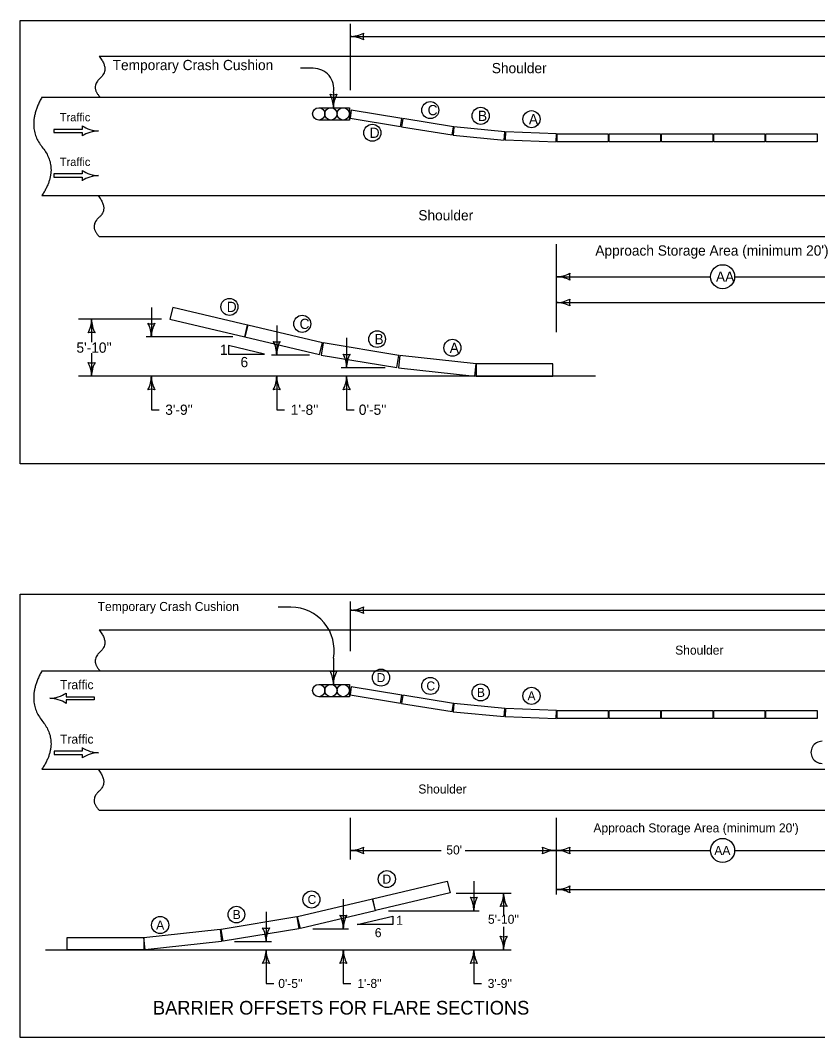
# Model space of a CAD drawing. Extents: x 8045 to 81668, y 6217 to 16762.
# Drawn here: x 13748 to 14916, y 6217 to 7708 of the extents above; entities that cross this region are included whole.
import ezdxf

# ---------------------------------------------------------------- set-up
doc = ezdxf.new("R2010")
doc.units = 0
for name, color, linetype in [('dsnNonPlotable', 7, 'Continuous'), ('dsnStdBlock', 7, 'Continuous'), ('dsnStdBlockModified', 7, 'Continuous'), ('dsnStdBorder', 7, 'Continuous'), ('dsnStdLineWork', 7, 'Continuous'), ('Level 5', 7, 'Continuous')]:
    doc.layers.add(name, color=color, linetype=linetype)

msp = doc.modelspace()

# ---------------------------------------------------------------- linework, layer by layer
at = {"layer": 'dsnNonPlotable'}
for p, q in [((14230.5, 7703.1), (14230.5, 7605.6)), ((14230.5, 7684.4), (15109, 7684.4)), ((13862.8, 7655.5), (14991.3, 7655.5)), ((14176.7, 7637.8), (14158, 7637.8)), ((13779.2, 7595.5), (15021.3, 7595.5)), ((14206.2, 7602.4), (14206.2, 7579.9)), ((14184.6, 7579.9), (14229.6, 7579.9)), ((14229.6, 7579.9), (14229.6, 7561.9)), ((14229.6, 7561.9), (14184.6, 7561.9)), ((14228.4, 7567.6), (14229.7, 7567.3)), ((14230.1, 7563.9), (14230.1, 7563.9)), ((13838.1, 7548.3), (13796.8, 7548.3)), ((13796.8, 7548.3), (13796.8, 7543.8)), ((13796.8, 7543.8), (13838.1, 7543.8)), ((13838.1, 7553.6), (13838.1, 7548.3)), ((13838.1, 7543.8), (13838.1, 7538.6)), ((13862, 7546.1), (13862, 7546.1)), ((13838.1, 7488.1), (13838.1, 7482.9)), ((13838.1, 7482.9), (13796.8, 7482.9)), ((13796.8, 7482.9), (13796.8, 7478.4)), ((13796.8, 7478.4), (13838.1, 7478.4)), ((13838.1, 7478.4), (13838.1, 7473.1)), ((13862, 7480.6), (13862, 7480.6)), ((13779.2, 7451.5), (15021.3, 7451.5)), ((13862.8, 7391.5), (14991.3, 7391.5)), ((14532.6, 7380.2), (14532.6, 7251.1)), ((14532.6, 7332.4), (14758.7, 7332.4)), ((14794, 7332.4), (15020.1, 7332.4)), ((14532.6, 7294.5), (15123.4, 7294.5)), ((13939.5, 7287.5), (13939.5, 7244.1)), ((13954.1, 7270), (13832.9, 7270)), ((13851.9, 7270), (13851.9, 7236.6)), ((14123.1, 7261.1), (14123.1, 7217.6)), ((14059, 7244.1), (13931.8, 7244.1)), ((14225.5, 7242.6), (14225.5, 7199.1)), ((13851.9, 7220.2), (13851.9, 7186.8)), ((14170.9, 7217.6), (14115.3, 7217.6)), ((14590.3, 7186.8), (13832.9, 7186.8)), ((13939.5, 7186.8), (13939.5, 7137.5)), ((14123.1, 7186.8), (14123.1, 7137.5)), ((14281.8, 7199.1), (14217.7, 7199.1)), ((14225.5, 7186.8), (14225.5, 7159.8)), ((14225.5, 7159.8), (14225.5, 7137.5)), ((13939.5, 7137.5), (13950.7, 7137.5)), ((14123.1, 7137.5), (14134.3, 7137.5)), ((14225.5, 7137.5), (14236.6, 7137.5))]:
    msp.add_line(p, q, dxfattribs=at)
for points in [[(14306.4, 7564.3), (14232.4, 7576.4), (14230.5, 7564.6), (14304.5, 7552.4)], [(14381.9, 7551.9), (14307.9, 7564), (14306, 7552.2), (14380, 7540.1)], [(14457.3, 7544.7), (14382.7, 7551.8), (14381.5, 7539.8), (14456.2, 7532.7)], [(14533.1, 7541.7), (14458.2, 7544.7), (14457.7, 7532.8), (14532.6, 7529.8)], [(14533.8, 7541.8), (14608.8, 7541.8), (14608.8, 7529.8), (14533.8, 7529.8)], [(14610.3, 7541.8), (14685.3, 7541.8), (14685.3, 7529.8), (14610.3, 7529.8)], [(14686.8, 7541.8), (14761.8, 7541.8), (14761.8, 7529.8), (14686.8, 7529.8)], [(14763.3, 7541.8), (14838.3, 7541.8), (14838.3, 7529.8), (14763.3, 7529.8)], [(14839.8, 7541.8), (14914.8, 7541.8), (14914.8, 7529.8), (14839.8, 7529.8)], [(14080.3, 7261.6), (13970.9, 7287.5), (13966.7, 7270), (14076.2, 7244.1)], [(14190.1, 7235.7), (14080.6, 7261.6), (14076.5, 7244.1), (14186, 7218.2)], [(14302.2, 7217), (14191.2, 7235.4), (14188.3, 7217.6), (14299.2, 7199.2)], [(14415.3, 7204.6), (14303.5, 7217), (14301.5, 7199.1), (14413.3, 7186.8)], [(14527.8, 7204.8), (14415.3, 7204.8), (14415.3, 7186.8), (14527.8, 7186.8)]]:
    msp.add_lwpolyline(points, close=True, dxfattribs=at)
for centre, radius in [((14348.1, 7576.5), 12.5), ((14184.6, 7570.9), 9), ((14184.6, 7570.9), 9), ((14202.6, 7570.9), 9), ((14202.6, 7570.9), 9), ((14220.6, 7570.9), 9), ((14220.6, 7570.9), 9), ((14421.9, 7568.1), 12.5), ((14496.4, 7563.2), 12.5), ((14263.2, 7543.3), 12.5), ((14776.4, 7332.4), 17.6), ((14053.8, 7288.2), 12.5), ((14160.5, 7263.3), 12.5), ((14270.2, 7240.9), 12.2), ((14380.5, 7228.3), 12.5)]:
    msp.add_circle(centre, radius, dxfattribs=at)
for centre, radius, start, end in [((14230.5, 7726.9), 42.5, 270, 298.0725), ((14230.5, 7641.9), 42.5, 61.9275, 90), ((14266.1, 7684.4), 16.4, 162.2666, 197.7334), ((14176.7, 7607.8), 30, 349.6463, 90), ((14206.2, 7615.5), 16.4, 252.2666, 287.7333), ((14163.7, 7579.9), 42.5, 360, 28.0725), ((14248.7, 7579.9), 42.5, 151.9275, 180), ((13864, 7594.4), 48.4, 237.618, 267.648), ((13864, 7497.7), 48.4, 92.352, 122.382), ((13864, 7528.9), 48.4, 237.618, 267.648), ((13864, 7432.3), 48.4, 92.352, 122.382), ((14532.6, 7374.9), 42.5, 270, 298.0725), ((14568.3, 7332.4), 16.4, 162.2666, 197.7334), ((14532.6, 7289.9), 42.5, 61.9275, 90), ((14532.6, 7337), 42.5, 270, 298.0725), ((14532.6, 7252), 42.5, 61.9275, 90), ((14568.3, 7294.5), 16.4, 162.2666, 197.7334), ((13809.4, 7270), 42.5, 331.9275, 0), ((13894.4, 7270), 42.5, 180, 208.0725), ((13939.5, 7279.7), 16.4, 252.2666, 287.7334), ((13897, 7244.1), 42.5, 0, 28.0725), ((13982, 7244.1), 42.5, 151.9275, 180), ((13851.9, 7234.4), 16.4, 72.2666, 107.7334), ((14123.1, 7253.3), 16.4, 252.2666, 287.7334), ((14080.6, 7217.6), 42.5, 0, 28.0725), ((14165.6, 7217.6), 42.5, 151.9275, 180), ((14225.5, 7234.7), 16.4, 252.2666, 287.7334), ((14183, 7199.1), 42.5, 0, 28.0725), ((14268, 7199.1), 42.5, 151.9275, 180), ((13851.9, 7222.4), 16.4, 252.2666, 287.7334), ((13809.4, 7186.8), 42.5, 0, 28.0725), ((13894.4, 7186.8), 42.5, 151.9275, 180), ((13897, 7186.8), 42.5, 331.9275, 0), ((13982, 7186.8), 42.5, 180, 208.0725), ((14080.6, 7186.8), 42.5, 331.9275, 0), ((14165.6, 7186.8), 42.5, 180, 208.0725), ((14183, 7186.8), 42.5, 331.9275, 0), ((14268, 7186.8), 42.5, 180, 208.0725), ((13939.5, 7151.1), 16.4, 72.2666, 107.7334), ((14123.1, 7151.1), 16.4, 72.2666, 107.7334), ((14225.5, 7151.1), 16.4, 72.2666, 107.7334)]:
    msp.add_arc(centre, radius, start, end, dxfattribs=at)
for points in [[(13862.8, 7655.5), (13878.9, 7636.1), (13850, 7610.5), (13864.4, 7595.5)], [(13779.2, 7595.5), (13754.6, 7552.8), (13805.3, 7490.6), (13779.2, 7451.5)], [(13861.2, 7451.4), (13877.3, 7432.1), (13848.4, 7406.5), (13862.8, 7391.5)]]:
    msp.add_open_spline(points, degree=2, dxfattribs=at)
at = {"layer": 'dsnStdBlock'}
msp.add_line((13747.5, 7708), (13747.5, 7708), dxfattribs=at)
at = {"layer": 'dsnStdBlockModified'}
for p, q in [((13747.5, 7708), (16852.5, 7708)), ((13747.5, 7058), (13747.5, 7708))]:
    msp.add_line(p, q, dxfattribs=at)
at = {"layer": 'dsnStdBorder'}
msp.add_line((16852.5, 7058), (13747.5, 7058), dxfattribs=at)
at = {"layer": 'dsnStdLineWork'}
for p, q in [((13747.5, 6867.4), (16852.5, 6867.4)), ((13747.5, 6217.4), (13747.5, 6867.4)), ((14143.9, 6848.2), (14125.2, 6848.2)), ((14230.5, 6856.5), (14230.5, 6783.9)), ((14230.5, 6843.7), (15163.3, 6843.7)), ((13862.8, 6814.8), (14991.3, 6814.8)), ((14206.2, 6773.5), (14206.2, 6734.9)), ((13779.2, 6754.8), (15021.3, 6754.8)), ((14184.6, 6734.9), (14229.6, 6734.9)), ((14229.6, 6734.9), (14229.6, 6716.9)), ((13790.7, 6714.6), (13790.7, 6714.6)), ((13814.6, 6722.1), (13814.6, 6716.9)), ((13814.6, 6716.9), (13855.9, 6716.9)), ((13855.9, 6712.4), (13814.6, 6712.4)), ((13814.6, 6712.4), (13814.6, 6707.1)), ((13855.9, 6716.9), (13855.9, 6712.4)), ((14229.6, 6716.9), (14184.6, 6716.9)), ((14228.4, 6722.6), (14229.7, 6722.3)), ((14230.1, 6718.9), (14230.1, 6718.9)), ((13838.3, 6637), (13797, 6637)), ((13797, 6637), (13797, 6632.5)), ((13838.3, 6642.3), (13838.3, 6637)), ((13862.2, 6634.8), (13862.2, 6634.8)), ((13797, 6632.5), (13838.3, 6632.5)), ((13838.3, 6632.5), (13838.3, 6627.3)), ((13779.2, 6610.8), (15021.3, 6610.8)), ((13862.8, 6550.8), (14991.3, 6550.8)), ((14230.5, 6539.5), (14230.5, 6478.3)), ((14532.6, 6539.5), (14532.6, 6427.1)), ((14230.5, 6491.7), (14363.9, 6491.7)), ((14399.2, 6491.7), (14532.6, 6491.7)), ((14532.6, 6491.7), (14758.7, 6491.7)), ((14794, 6491.7), (15020.1, 6491.7)), ((14411.9, 6446.8), (14411.9, 6403.4)), ((14386, 6429.3), (14466.4, 6429.3)), ((14455.5, 6429.3), (14455.5, 6395.9)), ((14532.6, 6434.6), (15123.4, 6434.6)), ((14220.7, 6420.4), (14220.7, 6377)), ((14107.5, 6401.9), (14107.5, 6358.4)), ((14240.8, 6383), (14293.4, 6395.4)), ((14287, 6403.4), (14419.7, 6403.4)), ((14293.4, 6395.4), (14293.4, 6383)), ((14293.4, 6383), (14240.8, 6383)), ((14175.8, 6377), (14228.5, 6377)), ((14455.5, 6379.5), (14455.5, 6346.1)), ((14061.5, 6358.4), (14115.3, 6358.4)), ((13784.5, 6346.1), (14466.4, 6346.1)), ((14107.5, 6346.1), (14107.5, 6319.1)), ((14220.7, 6346.1), (14220.7, 6296.8)), ((14411.9, 6346.1), (14411.9, 6296.8)), ((14107.5, 6319.1), (14107.5, 6296.8)), ((14107.5, 6296.8), (14118.7, 6296.8)), ((14220.7, 6296.8), (14231.9, 6296.8)), ((14411.9, 6296.8), (14423, 6296.8)), ((16852.5, 6217.4), (13747.5, 6217.4))]:
    msp.add_line(p, q, dxfattribs=at)
for points in [[(14306.4, 6719.3), (14232.4, 6731.4), (14230.5, 6719.6), (14304.5, 6707.5)], [(14381.9, 6706.9), (14307.9, 6719.1), (14306, 6707.2), (14380, 6695.1)], [(14457.3, 6699.7), (14382.7, 6706.8), (14381.5, 6694.9), (14456.2, 6687.8)], [(14533.1, 6696.8), (14458.2, 6699.8), (14457.7, 6687.8), (14532.6, 6684.8)], [(14533.8, 6696.8), (14608.8, 6696.8), (14608.8, 6684.8), (14533.8, 6684.8)], [(14610.3, 6696.8), (14685.3, 6696.8), (14685.3, 6684.8), (14610.3, 6684.8)], [(14686.8, 6696.8), (14761.8, 6696.8), (14761.8, 6684.8), (14686.8, 6684.8)], [(14763.3, 6696.8), (14838.3, 6696.8), (14838.3, 6684.8), (14763.3, 6684.8)], [(14839.8, 6696.8), (14914.8, 6696.8), (14914.8, 6684.8), (14839.8, 6684.8)], [(14263.5, 6421), (14373, 6446.9), (14377.2, 6429.4), (14267.7, 6403.5)], [(14153.7, 6395), (14263.2, 6420.9), (14267.3, 6403.4), (14157.9, 6377.5)], [(14041.6, 6376.3), (14152.6, 6394.7), (14155.6, 6377), (14044.6, 6358.5)], [(13928.5, 6364), (14040.4, 6376.3), (14042.3, 6358.4), (13930.5, 6346.1)], [(13816, 6364.2), (13928.5, 6364.1), (13928.5, 6346.1), (13816, 6346.2)]]:
    msp.add_lwpolyline(points, close=True, dxfattribs=at)
for centre, radius in [((14275.9, 6744.9), 12.5), ((14348.1, 6732.7), 12.5), ((14184.6, 6725.9), 9), ((14184.6, 6725.9), 9), ((14202.6, 6725.9), 9), ((14202.6, 6725.9), 9), ((14220.6, 6725.9), 9), ((14220.6, 6725.9), 9), ((14421.9, 6723.2), 12.5), ((14496.4, 6718.2), 12.5), ((14776.4, 6491.7), 17.6), ((14284.4, 6449.7), 12.5), ((14174, 6419.8), 12.5), ((14064, 6397.7), 12.2), ((13952.4, 6382.4), 12.5)]:
    msp.add_circle(centre, radius, dxfattribs=at)
for centre, radius, start, end in [((14143.9, 6784.9), 63.3, 349.6463, 90), ((14230.5, 6886.2), 42.5, 270, 298.0725), ((14230.5, 6801.2), 42.5, 61.9275, 90), ((14266.1, 6843.7), 16.4, 162.2666, 197.7334), ((14206.2, 6770.5), 16.4, 252.2666, 287.7333), ((14163.7, 6734.9), 42.5, 360, 28.0725), ((14248.7, 6734.9), 42.5, 151.9275, 180), ((13788.7, 6763), 48.4, 272.352, 302.382), ((13788.7, 6666.3), 48.4, 57.618, 87.648), ((13864.2, 6683.1), 48.4, 237.618, 267.648), ((13864.2, 6586.5), 48.4, 92.352, 122.382), ((14230.5, 6534.2), 42.5, 270, 298.0725), ((14230.5, 6449.2), 42.5, 61.9275, 90), ((14266.1, 6491.7), 16.4, 162.2666, 197.7334), ((14497, 6491.7), 16.4, 342.2666, 17.7333), ((14532.6, 6534.2), 42.5, 241.9275, 270), ((14532.6, 6449.2), 42.5, 90, 118.0725), ((14532.6, 6534.2), 42.5, 270, 298.0725), ((14532.6, 6449.2), 42.5, 61.9275, 90), ((14568.3, 6491.7), 16.4, 162.2666, 197.7334), ((14413, 6429.3), 42.5, 331.9275, 360), ((14498, 6429.3), 42.5, 180, 208.0725), ((14532.6, 6477.1), 42.5, 270, 298.0725), ((14532.6, 6392.1), 42.5, 61.9275, 90), ((14568.3, 6434.6), 16.4, 162.2666, 197.7334), ((14411.9, 6439), 16.4, 252.2666, 287.7333), ((14369.4, 6403.4), 42.5, 360, 28.0725), ((14454.4, 6403.4), 42.5, 151.9275, 180), ((14455.5, 6393.7), 16.4, 72.2666, 107.7334), ((14220.7, 6412.6), 16.4, 252.2666, 287.7333), ((14178.2, 6377), 42.5, 360, 28.0725), ((14263.2, 6377), 42.5, 151.9275, 180), ((14107.5, 6394), 16.4, 252.2666, 287.7333), ((14065, 6358.4), 42.5, 360, 28.0725), ((14150, 6358.4), 42.5, 151.9275, 180), ((14455.5, 6381.7), 16.4, 252.2666, 287.7333), ((14413, 6346.1), 42.5, 360, 28.0725), ((14498, 6346.1), 42.5, 151.9275, 180), ((14065, 6346.1), 42.5, 331.9275, 360), ((14150, 6346.1), 42.5, 180, 208.0725), ((14178.2, 6346.1), 42.5, 331.9275, 360), ((14263.2, 6346.1), 42.5, 180, 208.0725), ((14369.4, 6346.1), 42.5, 331.9275, 360), ((14454.4, 6346.1), 42.5, 180, 208.0725), ((14107.5, 6310.4), 16.4, 72.2666, 107.7334), ((14220.7, 6310.4), 16.4, 72.2666, 107.7334), ((14411.9, 6310.4), 16.4, 72.2666, 107.7334)]:
    msp.add_arc(centre, radius, start, end, dxfattribs=at)
msp.add_ellipse((14922.1, 6635.4), major_axis=(-16.3, 0), ratio=0.995025, start_param=4.712389, end_param=7.853982, dxfattribs=at)
for points in [[(13862.8, 6814.8), (13878.9, 6795.5), (13850, 6769.8), (13864.4, 6754.8)], [(13779.2, 6754.8), (13754.6, 6712.1), (13805.3, 6649.9), (13779.2, 6610.8)], [(13861.2, 6610.7), (13877.3, 6591.4), (13848.4, 6565.8), (13862.8, 6550.8)]]:
    msp.add_open_spline(points, degree=2, dxfattribs=at)
at = {"layer": 'Level 5'}
for p, q in [((14105.1, 7219.1), (14052.5, 7231.5)), ((14052.5, 7231.5), (14052.5, 7219.1)), ((14052.5, 7219.1), (14105.1, 7219.1))]:
    msp.add_line(p, q, dxfattribs=at)

# ---------------------------------------------------------------- texts
at = {"layer": 'dsnStdLineWork'}
for s, height, p in [('Temporary Crash Cushion', 13.2, (13860.8, 6842.6)), ('Shoulder', 13.2, (14706.9, 6778.6)), ('Traffic', 13.2, (13805.7, 6728)), ('D', 13.2, (14269.6, 6738.3)), ('C', 13.2, (14342.4, 6726.1)), ('B', 13.2, (14416.4, 6716.6)), ('A', 13.2, (14490.5, 6711.6)), ('Traffic', 13.2, (13805.7, 6648.2)), ('Shoulder', 13.2, (14330.6, 6575.1)), ("Approach Storage Area (minimum 20')", 13.2, (14587.1, 6518.1)), ("50'", 13.2, (14371.6, 6485.8)), ('AA', 13.2, (14764.2, 6485.1)), ('D', 13.2, (14278.1, 6443.1)), ('C', 13.2, (14168.3, 6413.2)), ('B', 13.2, (14058.6, 6391.1)), ('1', 13.2, (14298.1, 6382.7)), ("5'-10''", 13.2, (14432.6, 6384.2)), ('A', 13.2, (13946.5, 6375.8)), ('6', 13.2, (14266.8, 6364.6)), ("0'-5''", 13.2, (14125.4, 6290.2)), ("1'-8''", 13.2, (14241.3, 6290.2)), ("3'-9''", 13.2, (14432.2, 6290.2)), ('BARRIER OFFSETS FOR FLARE SECTIONS', 20, (13941.8, 6251.2))]:
    msp.add_text(s, height=height, dxfattribs=at).set_placement(p)
at = {"layer": 'Level 5'}
for s, height, p in [('Temporary Crash Cushion', 15, (13882.8, 7635.1)), ('Shoulder', 15, (14438.2, 7630.6)), ('C', 15, (14344.2, 7569)), ('B', 15, (14418, 7560.6)), ('Traffic', 12, (13805.5, 7560.1)), ('A', 15, (14492.5, 7555.7)), ('D', 15, (14259.3, 7535.8)), ('Traffic', 12, (13805.5, 7494.6)), ('Shoulder', 15, (14330.6, 7414.9)), ("Approach Storage Area (minimum 20')", 15, (14589.9, 7363.3)), ('AA', 15, (14766.6, 7324.9)), ('D', 15, (14049.9, 7280.7)), ('C', 15, (14156.6, 7255.8)), ('B', 15, (14266.3, 7233.5)), ("5'-10''", 15, (13829.7, 7221)), ('1', 15, (14039.9, 7217.9)), ('A', 15, (14376.6, 7220.8)), ('6', 15, (14070.1, 7199.8)), ("3'-9''", 15, (13959.8, 7130)), ("1'-8''", 15, (14143.7, 7130)), ("0'-5''", 15, (14243.4, 7130))]:
    msp.add_text(s, height=height, dxfattribs=at).set_placement(p)

doc.saveas('drawing.dxf')
